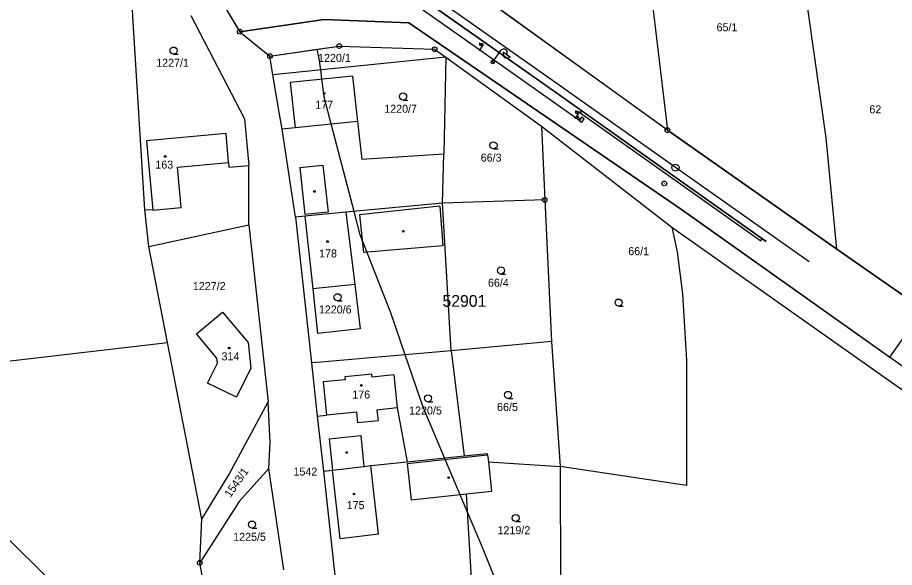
# Model space of a CAD drawing. Extents: x -777175 to -776673, y -1110537 to -1110036.
# Drawn here: x -776987.6 to -776801.4, y -1110431.1 to -1110314.3 of the extents above; entities that cross this region are included whole.
import ezdxf

# ---------------------------------------------------------------- set-up
doc = ezdxf.new("R2010")
doc.units = 0
for name, color, linetype in [('BPEJ', 7, 'Continuous'), ('GD_Demolice', 7, 'Continuous'), ('GD_Nový stav', 7, 'Continuous'), ('GD_Starý stav', 7, 'Continuous'), ('Katastr_HRANICE DRÁHY', 7, 'Continuous'), ('Katastr_Hranice parcel', 7, 'Continuous'), ('Katastr_Parcelní čísla', 7, 'Continuous'), ('Katastr_pozemek SŽDC_šrafy', 7, 'Continuous'), ('Katastr_Slučkované čáry', 7, 'Continuous'), ('Katastr_Značky kultur', 7, 'Continuous'), ('Vrstva 7', 7, 'Continuous')]:
    doc.layers.add(name, color=color, linetype=linetype)

msp = doc.modelspace()

# ---------------------------------------------------------------- linework, layer by layer
at = {"layer": 'BPEJ'}
for points in [[(-776780.63, -1110277.66), (-776801.34, -1110279.1), (-776814.49, -1110280.25), (-776823.89, -1110281.93), (-776826.29, -1110267.5), (-776831.4, -1110267.85), (-776830.95, -1110273.53), (-776856.55, -1110275.29), (-776856.32, -1110281.19), (-776854.31, -1110299.08), (-776849.62, -1110338.22), (-776894.76, -1110305.65), (-776896.59, -1110304.32), (-776903.91, -1110299.01), (-776906.52, -1110296.78), (-776914.36, -1110290.06), (-776923.15, -1110282.87), (-776931.82, -1110275.9)], [(-776942.64, -1110471.49), (-776943.89, -1110463.76), (-776944.49, -1110457.52), (-776946.46, -1110445.63), (-776946.62, -1110444.42), (-776947.54, -1110437.37), (-776947.6, -1110436.89), (-776948.9, -1110430.12), (-776948.48, -1110420.89), (-776959.71, -1110362.93), (-776960.61, -1110355.15), (-776963.07, -1110315.22), (-776964.17, -1110295.07), (-776960.44, -1110293.63), (-776956.24, -1110294.15), (-776954.44, -1110298.36), (-776953.88, -1110294.2), (-776949.89, -1110285), (-776940.9, -1110291.45)], [(-776940.9, -1110291.45), (-776945.85, -1110300.04), (-776946.2, -1110307.65), (-776940.41, -1110317.34), (-776934.03, -1110322.5), (-776924.02, -1110321.07)], [(-776924.02, -1110321.07), (-776919.29, -1110320.39), (-776899.05, -1110321.06), (-776896.7, -1110322.75), (-776876.4, -1110337.37), (-776875.66, -1110353.06), (-776874.23, -1110383.12), (-776872.38, -1110409.66), (-776872.36, -1110434.4)], [(-776871.27, -1110465.42), (-776878.74, -1110452.04), (-776879.88, -1110449.23), (-776883.66, -1110439.87), (-776885.8, -1110434.57), (-776888.9, -1110426.9), (-776892.08, -1110419.38), (-776896.95, -1110407.86), (-776901.52, -1110397.06), (-776905.33, -1110385.94), (-776908.38, -1110377.06), (-776914.87, -1110360.44), (-776916.16, -1110355.5), (-776922.42, -1110331.54), (-776922.97, -1110327.43), (-776923.23, -1110325.46), (-776923.55, -1110323.06), (-776924.02, -1110321.07)]]:
    msp.add_lwpolyline(points, dxfattribs=at)
at = {"layer": 'Defpoints'}
msp.add_line((-776876.14, -1110537.25), (-777174.79, -1110241.95), dxfattribs=at)
at = {"layer": 'GD_Demolice'}
for p, q in [((-776886.5, -1110323.47), (-776884.98, -1110321.33)), ((-776884.55, -1110321.64), (-776882.96, -1110322.76)), ((-776887.07, -1110323.67), (-776886.42, -1110323.55)), ((-776887.05, -1110323.94), (-776886.34, -1110323.82))]:
    msp.add_line(p, q, dxfattribs=at)
msp.add_lwpolyline([(-776868.13, -1110334.57), (-776829.78, -1110361.74), (-776829.49, -1110361.33), (-776867.84, -1110334.16)], close=True, dxfattribs=at)
msp.add_circle((-776886.71, -1110323.78), 0.375, dxfattribs=at)
msp.add_circle((-776886.71, -1110323.78), 0.375, dxfattribs=at)
for centre, start, end in [((-776884.37, -1110321.76), 324.7342, 144.7342), ((-776883.76, -1110322.21), 144.0316, 325.4368)]:
    msp.add_arc(centre, 0.75, start, end, dxfattribs=at)
at = {"layer": 'GD_Nový stav'}
for p, q in [((-776909.86, -1110306.76), (-776889.46, -1110321.21)), ((-776888.97, -1110320.18), (-776889.57, -1110319.75)), ((-776889.38, -1110321.09), (-776888.81, -1110320.29)), ((-776889.48, -1110321.35), (-776889.52, -1110321.08)), ((-776889.46, -1110321.21), (-776868.26, -1110336.2)), ((-776889.38, -1110321.32), (-776889.42, -1110321.08)), ((-776868.58, -1110334.6), (-776869.18, -1110334.17)), ((-776868.99, -1110335.51), (-776868.42, -1110334.71)), ((-776868.59, -1110335.23), (-776868.81, -1110335.53)), ((-776868.13, -1110334.57), (-776867.84, -1110334.16)), ((-776869.09, -1110335.77), (-776869.13, -1110335.5)), ((-776868.98, -1110335.74), (-776869.02, -1110335.5)), ((-776868.7, -1110335.38), (-776868.09, -1110335.81)), ((-776868.09, -1110335.81), (-776868.34, -1110336.17)), ((-776868.34, -1110336.17), (-776867.83, -1110336.53)), ((-776867.84, -1110335.46), (-776868.09, -1110335.81)), ((-776867.33, -1110335.82), (-776867.84, -1110335.46)), ((-776867.83, -1110336.53), (-776867.33, -1110335.82))]:
    msp.add_line(p, q, dxfattribs=at)
for centre in [(-776889.46, -1110321.21), (-776889.46, -1110321.21), (-776869.07, -1110335.63), (-776869.07, -1110335.63)]:
    msp.add_circle(centre, 0.141, dxfattribs=at)
for centre, start, end in [((-776889.27, -1110319.97), 143.98, 325.3852), ((-776889.04, -1110320.13), 324.6826, 144.6826), ((-776868.88, -1110334.39), 143.98, 325.3852), ((-776868.65, -1110334.55), 324.6826, 144.6826)]:
    msp.add_arc(centre, 0.281, start, end, dxfattribs=at)
at = {"layer": 'GD_Starý stav'}
for points in [[(-776933.32, -1110287.93), (-776932.41, -1110288.39), (-776916.53, -1110299.75), (-776903.36, -1110309.07), (-776875.06, -1110329), (-776849.25, -1110347.3), (-776828.68, -1110361.9)], [(-776828.68, -1110361.9), (-776829.18, -1110361.55), (-776849.26, -1110347.33), (-776875, -1110329.07), (-776903.43, -1110309.03), (-776920.48, -1110296.98), (-776932.53, -1110288.41), (-776933.32, -1110287.93)], [(-776819.55, -1110366.24), (-776848.4, -1110345.85), (-776874.05, -1110327.7), (-776902.43, -1110307.63), (-776922.25, -1110293.6), (-776926.74, -1110290.42), (-776929.88, -1110288.2)]]:
    msp.add_lwpolyline(points, dxfattribs=at)
at = {"layer": 'Katastr_HRANICE DRÁHY'}
for points in [[(-776849.62, -1110338.22), (-776894.76, -1110305.65)], [(-776946.2, -1110307.65), (-776940.41, -1110317.34)], [(-776757.91, -1110417.68), (-776792.98, -1110393.16), (-776846.61, -1110355.09), (-776904.52, -1110315.47), (-776922.51, -1110314.75), (-776940.41, -1110317.34)], [(-776849.62, -1110338.22), (-776813.64, -1110363.55), (-776795.25, -1110376.34), (-776788.84, -1110380.33), (-776748.99, -1110408.66)]]:
    msp.add_lwpolyline(points, dxfattribs=at)
at = {"layer": 'Katastr_Hranice parcel'}
for points in [[(-776813.64, -1110363.55), (-776815.92, -1110339.86), (-776822.21, -1110295.34), (-776823.89, -1110281.93)], [(-776963.07, -1110315.22), (-776964.17, -1110295.07)], [(-776854.31, -1110299.08), (-776849.62, -1110338.22)], [(-776950.83, -1110313.89), (-776939.43, -1110335.86)], [(-776960.61, -1110355.15), (-776963.07, -1110315.22)], [(-776940.41, -1110317.34), (-776934.03, -1110322.5)], [(-776934.03, -1110322.5), (-776919.29, -1110320.39)], [(-776919.29, -1110320.39), (-776899.05, -1110321.06)], [(-776899.05, -1110321.06), (-776896.7, -1110322.75)], [(-776933.39, -1110326.49), (-776934.03, -1110322.5)], [(-776896.7, -1110322.75), (-776929.92, -1110326.14)], [(-776896.7, -1110322.75), (-776897.12, -1110343.35)], [(-776896.7, -1110322.75), (-776876.4, -1110337.37)], [(-776929.92, -1110326.14), (-776933.39, -1110326.49)], [(-776931.99, -1110334.85), (-776933.39, -1110326.49)], [(-776916.46, -1110326.75), (-776929.7, -1110328.14)], [(-776916.46, -1110326.75), (-776915.42, -1110336.37)], [(-776929.7, -1110328.14), (-776928.66, -1110337.76)], [(-776931.45, -1110338.05), (-776931.99, -1110334.85)], [(-776939.43, -1110335.86), (-776938.47, -1110345.76)], [(-776915.42, -1110336.37), (-776914.54, -1110344.5)], [(-776943.34, -1110338.96), (-776960.2, -1110340.54)], [(-776942.8, -1110345.12), (-776943.34, -1110338.96)], [(-776928.66, -1110337.76), (-776931.45, -1110338.05)], [(-776928.57, -1110356.7), (-776931.45, -1110338.05)], [(-776876.4, -1110337.37), (-776875.66, -1110353.06)], [(-776876.4, -1110337.37), (-776848.72, -1110358.87), (-776847.56, -1110364.06), (-776846.44, -1110372.99), (-776845.59, -1110387.18), (-776845.59, -1110413.73), (-776872.38, -1110409.66)], [(-776960.2, -1110340.54), (-776958.86, -1110355.2)], [(-776897.12, -1110343.35), (-776914.54, -1110344.5)], [(-776897.39, -1110353.76), (-776897.12, -1110343.35)], [(-776942.8, -1110345.12), (-776942.71, -1110346.13)], [(-776942.71, -1110346.13), (-776938.47, -1110345.76)], [(-776938.51, -1110358.35), (-776938.47, -1110345.76)], [(-776897.39, -1110353.76), (-776917.87, -1110355.66)], [(-776875.66, -1110353.06), (-776897.39, -1110353.76)], [(-776895.52, -1110385.09), (-776897.39, -1110353.76)], [(-776875.66, -1110353.06), (-776874.23, -1110383.12)], [(-776959.71, -1110362.93), (-776960.61, -1110355.15)], [(-776958.86, -1110355.2), (-776960.61, -1110355.15)], [(-776917.87, -1110355.66), (-776926.58, -1110356.51)], [(-776926.58, -1110356.51), (-776928.57, -1110356.7)], [(-776928.57, -1110356.7), (-776925.21, -1110387.65)], [(-776959.71, -1110362.93), (-776938.51, -1110358.35)], [(-776938.51, -1110358.35), (-776934.37, -1110395.94)], [(-776848.72, -1110358.87), (-776760.96, -1110420.76)], [(-776948.48, -1110420.89), (-776959.71, -1110362.93)], [(-776915.99, -1110371.01), (-776924.93, -1110371.95)], [(-776924.93, -1110371.95), (-776923.89, -1110381.39)], [(-776915.99, -1110371.01), (-776914.84, -1110380.44)], [(-776949.58, -1110381.53), (-776944.06, -1110376.89)], [(-776944.06, -1110376.89), (-776938.61, -1110383.37)], [(-776945.3, -1110386.64), (-776949.58, -1110381.53)], [(-776914.84, -1110380.44), (-776923.89, -1110381.39)], [(-777023.74, -1110391.3), (-776955.76, -1110383.34)], [(-776938.61, -1110383.37), (-776938.08, -1110388.81)], [(-776874.23, -1110383.12), (-776895.52, -1110385.09)], [(-776874.23, -1110383.12), (-776872.38, -1110409.66)], [(-776895.52, -1110385.09), (-776923.22, -1110387.48)], [(-776895.52, -1110385.09), (-776892.79, -1110407.42)], [(-776945.17, -1110387.71), (-776945.3, -1110386.64)], [(-776947.29, -1110391.94), (-776945.17, -1110387.71)], [(-776938.08, -1110388.81), (-776941.13, -1110394.94)], [(-776923.22, -1110387.48), (-776925.21, -1110387.65)], [(-776925.21, -1110387.65), (-776923.96, -1110398.98)], [(-776912.36, -1110390.08), (-776918.11, -1110390.66)], [(-776918.11, -1110390.66), (-776918.05, -1110391.25)], [(-776912.3, -1110390.67), (-776912.36, -1110390.08)], [(-776907.75, -1110390.21), (-776912.3, -1110390.67)], [(-776907.75, -1110390.21), (-776907.04, -1110397.24)], [(-776941.13, -1110394.94), (-776947.29, -1110391.94)], [(-776918.05, -1110391.25), (-776922.7, -1110391.72)], [(-776922.7, -1110391.72), (-776922.03, -1110398.78)], [(-776942.73, -1110411.46), (-776934.37, -1110395.94)], [(-776933.98, -1110404.58), (-776934.37, -1110395.94)], [(-776907.04, -1110397.24), (-776904.88, -1110408.71)], [(-776923.96, -1110398.98), (-776922.03, -1110398.78)], [(-776923.96, -1110398.98), (-776922.67, -1110410.67)], [(-776934.24, -1110410.08), (-776933.98, -1110404.58)], [(-776904.88, -1110408.71), (-776892.79, -1110407.42)], [(-776892.79, -1110407.42), (-776887.83, -1110406.89)], [(-776887.8, -1110407.19), (-776887.83, -1110406.89)], [(-776887.8, -1110407.19), (-776887.64, -1110408.68)], [(-776920.73, -1110410.44), (-776914.08, -1110409.64)], [(-776914.08, -1110409.64), (-776912.57, -1110409.46)], [(-776912.57, -1110409.46), (-776904.88, -1110408.71)], [(-776887.64, -1110408.68), (-776872.38, -1110409.66)], [(-776887.64, -1110408.68), (-776886.97, -1110414.92)], [(-776872.38, -1110409.66), (-776872.36, -1110434.4)], [(-776948.48, -1110420.89), (-776942.73, -1110411.46)], [(-776934.24, -1110410.08), (-776940.56, -1110417.1)], [(-776931.08, -1110431.61), (-776934.24, -1110410.08)], [(-776922.67, -1110410.67), (-776920.73, -1110410.44)], [(-776922.67, -1110410.67), (-776919.72, -1110437.38)], [(-776892.31, -1110415.49), (-776886.97, -1110414.92)], [(-776940.56, -1110417.1), (-776948.9, -1110430.12)], [(-776891.17, -1110434.64), (-776892.31, -1110415.49)], [(-776948.9, -1110430.12), (-776948.48, -1110420.89)], [(-776947.6, -1110436.89), (-776948.9, -1110430.12)]]:
    msp.add_lwpolyline(points, dxfattribs=at)
at = {"layer": 'Katastr_pozemek SŽDC_šrafy'}
for p, q in [((-776850.02, -1110337.93), (-776894.36, -1110305.94)), ((-776945.94, -1110308.08), (-776940.67, -1110316.91))]:
    msp.add_line(p, q, dxfattribs=at)
msp.add_lwpolyline([(-776939.92, -1110317.27), (-776922.51, -1110314.75), (-776904.52, -1110315.47), (-776846.61, -1110355.09), (-776802.43, -1110386.46), (-776795.25, -1110376.34), (-776813.64, -1110363.55), (-776849.21, -1110338.51)], dxfattribs=at)
for centre, start, end in [((-776940.41, -1110317.34), 8.2296, 120.8593), ((-776849.62, -1110338.22), 144.1883, 180), ((-776849.62, -1110338.22), 180, 324.8604)]:
    msp.add_arc(centre, 0.499, start, end, dxfattribs=at)
at = {"layer": 'Katastr_Slučkované čáry'}
for points in [[(-776915.42, -1110336.37), (-776928.66, -1110337.76)], [(-776953.66, -1110346.08), (-776942.8, -1110345.12)], [(-776952.88, -1110354.65), (-776953.66, -1110346.08)], [(-776927.7, -1110346.2), (-776922.76, -1110345.68)], [(-776927.7, -1110346.2), (-776926.64, -1110356.16)], [(-776922.76, -1110345.68), (-776921.68, -1110355.68)], [(-776958.86, -1110355.2), (-776952.88, -1110354.65)], [(-776921.68, -1110355.68), (-776926.64, -1110356.16)], [(-776917.87, -1110355.66), (-776915.99, -1110371.01)], [(-776897.95, -1110354.4), (-776914.98, -1110356.23)], [(-776897.95, -1110354.4), (-776897.3, -1110362.8)], [(-776926.58, -1110356.51), (-776924.93, -1110371.95)], [(-776914.98, -1110356.23), (-776914.17, -1110364.23)], [(-776897.3, -1110362.8), (-776914.17, -1110364.23)], [(-776915.6, -1110398.12), (-776922.03, -1110398.78)], [(-776915.36, -1110400.39), (-776915.6, -1110398.12)], [(-776907.04, -1110397.24), (-776911.29, -1110397.68)], [(-776911.29, -1110397.68), (-776911.06, -1110399.95)], [(-776911.06, -1110399.95), (-776915.36, -1110400.39)], [(-776921.41, -1110403.78), (-776914.74, -1110403.1)], [(-776921.41, -1110403.78), (-776920.73, -1110410.44)], [(-776914.74, -1110403.1), (-776914.08, -1110409.64)], [(-776904.85, -1110409.01), (-776887.8, -1110407.19)], [(-776910.98, -1110424.03), (-776912.57, -1110409.46)], [(-776904.85, -1110409.01), (-776904.02, -1110416.74)], [(-776919.14, -1110425.01), (-776920.73, -1110410.44)], [(-776904.02, -1110416.74), (-776892.31, -1110415.49)], [(-776910.98, -1110424.03), (-776919.14, -1110425.01)]]:
    msp.add_lwpolyline(points, dxfattribs=at)
at = {"layer": 'Katastr_Značky kultur'}
for p, q in [((-776940.46, -1110317.34), (-776940.36, -1110317.34)), ((-776954.48, -1110322.08), (-776953.48, -1110322.08)), ((-776919.34, -1110320.39), (-776919.24, -1110320.39)), ((-776899.1, -1110321.06), (-776899, -1110321.06)), ((-776934.08, -1110322.5), (-776933.98, -1110322.5)), ((-776905.75, -1110331.84), (-776904.75, -1110331.84)), ((-776849.67, -1110338.22), (-776849.57, -1110338.22)), ((-776886.56, -1110342.22), (-776885.56, -1110342.22)), ((-776875.71, -1110353.06), (-776875.61, -1110353.06)), ((-776884.98, -1110368.79), (-776883.98, -1110368.79)), ((-776919.67, -1110374.47), (-776918.67, -1110374.47)), ((-776860, -1110375.61), (-776859, -1110375.61)), ((-776900.47, -1110395.93), (-776899.47, -1110395.93)), ((-776883.47, -1110395.21), (-776882.47, -1110395.21)), ((-776937.82, -1110422.75), (-776936.82, -1110422.75)), ((-776881.84, -1110421.35), (-776880.84, -1110421.35)), ((-776948.95, -1110430.12), (-776948.85, -1110430.12))]:
    msp.add_line(p, q, dxfattribs=at)
for centre, radius in [((-776940.41, -1110317.34), 0.499), ((-776919.29, -1110320.39), 0.499), ((-776954.48, -1110321.33), 0.75), ((-776934.03, -1110322.5), 0.499), ((-776899.05, -1110321.06), 0.499), ((-776922.51, -1110330.42), 0.175), ((-776905.75, -1110331.09), 0.75), ((-776849.62, -1110338.22), 0.499), ((-776886.56, -1110341.47), 0.75), ((-776956.26, -1110343.82), 0.175), ((-776924.56, -1110351.26), 0.175), ((-776875.66, -1110353.06), 0.499), ((-776905.7, -1110359.7), 0.175), ((-776921.79, -1110361.89), 0.175), ((-776884.98, -1110368.04), 0.75), ((-776919.67, -1110373.72), 0.75), ((-776860, -1110374.86), 0.75), ((-776942.66, -1110384.53), 0.175), ((-776914.6, -1110392.46), 0.175), ((-776900.47, -1110395.18), 0.75), ((-776883.47, -1110394.46), 0.75), ((-776917.74, -1110406.7), 0.175), ((-776896.07, -1110412.03), 0.175), ((-776916.16, -1110415.5), 0.175), ((-776881.84, -1110420.6), 0.75), ((-776937.82, -1110422), 0.75), ((-776948.9, -1110430.12), 0.499)]:
    msp.add_circle(centre, radius, dxfattribs=at)
at = {"layer": 'Vrstva 7'}
msp.add_line((-776850.24, -1110349.57), (-776850.33, -1110349.51), dxfattribs=at)
for centre, radius in [((-776847.92, -1110346.19), 0.75), ((-776850.29, -1110349.54), 0.5)]:
    msp.add_circle(centre, radius, dxfattribs=at)

# ---------------------------------------------------------------- texts
at = {"layer": 'BPEJ'}
msp.add_text('52901', height=2.5, dxfattribs=at).set_placement((-776897.38, -1110375.76))
at = {"layer": 'Katastr_Parcelní čísla'}
for s, p in [('65/1', (-776839.2, -1110317.24)), ('1220/1', (-776923.8, -1110323.74)), ('1227/1', (-776958.16, -1110324.78)), ('177', (-776924.38, -1110333.69)), ('1220/7', (-776909.75, -1110334.54)), ('62', (-776806.76, -1110334.67)), ('66/3', (-776889.27, -1110344.92)), ('163', (-776958.35, -1110346.41)), ('66/1', (-776857.95, -1110364.79)), ('178', (-776923.58, -1110365.28)), ('1227/2', (-776950.38, -1110372.2)), ('66/4', (-776887.73, -1110371.49)), ('1220/6', (-776923.63, -1110377.17)), ('314', (-776944.29, -1110387.13)), ('176', (-776916.53, -1110395.24)), ('66/5', (-776885.8, -1110397.88)), ('1220/5', (-776904.47, -1110398.63)), ('1542', (-776929.02, -1110411.6)), ('175', (-776917.72, -1110418.73)), ('1219/2', (-776885.7, -1110424.05)), ('1225/5', (-776941.82, -1110425.45))]:
    msp.add_text(s, height=1.7, dxfattribs=at).set_placement(p)
msp.add_text('1543/1', height=1.7, rotation=55.0543, dxfattribs=at).set_placement((-776942.42, -1110416.39))

doc.saveas('drawing.dxf')
